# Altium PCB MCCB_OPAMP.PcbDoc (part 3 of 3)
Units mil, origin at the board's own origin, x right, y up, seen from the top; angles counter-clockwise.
Board outline 3937.01 x 3937.01 mil, 2 copper layers (Top Layer, Bottom Layer), stack 62 mil thick; 238 components, 115 nets, 518 pads, 159 vias.
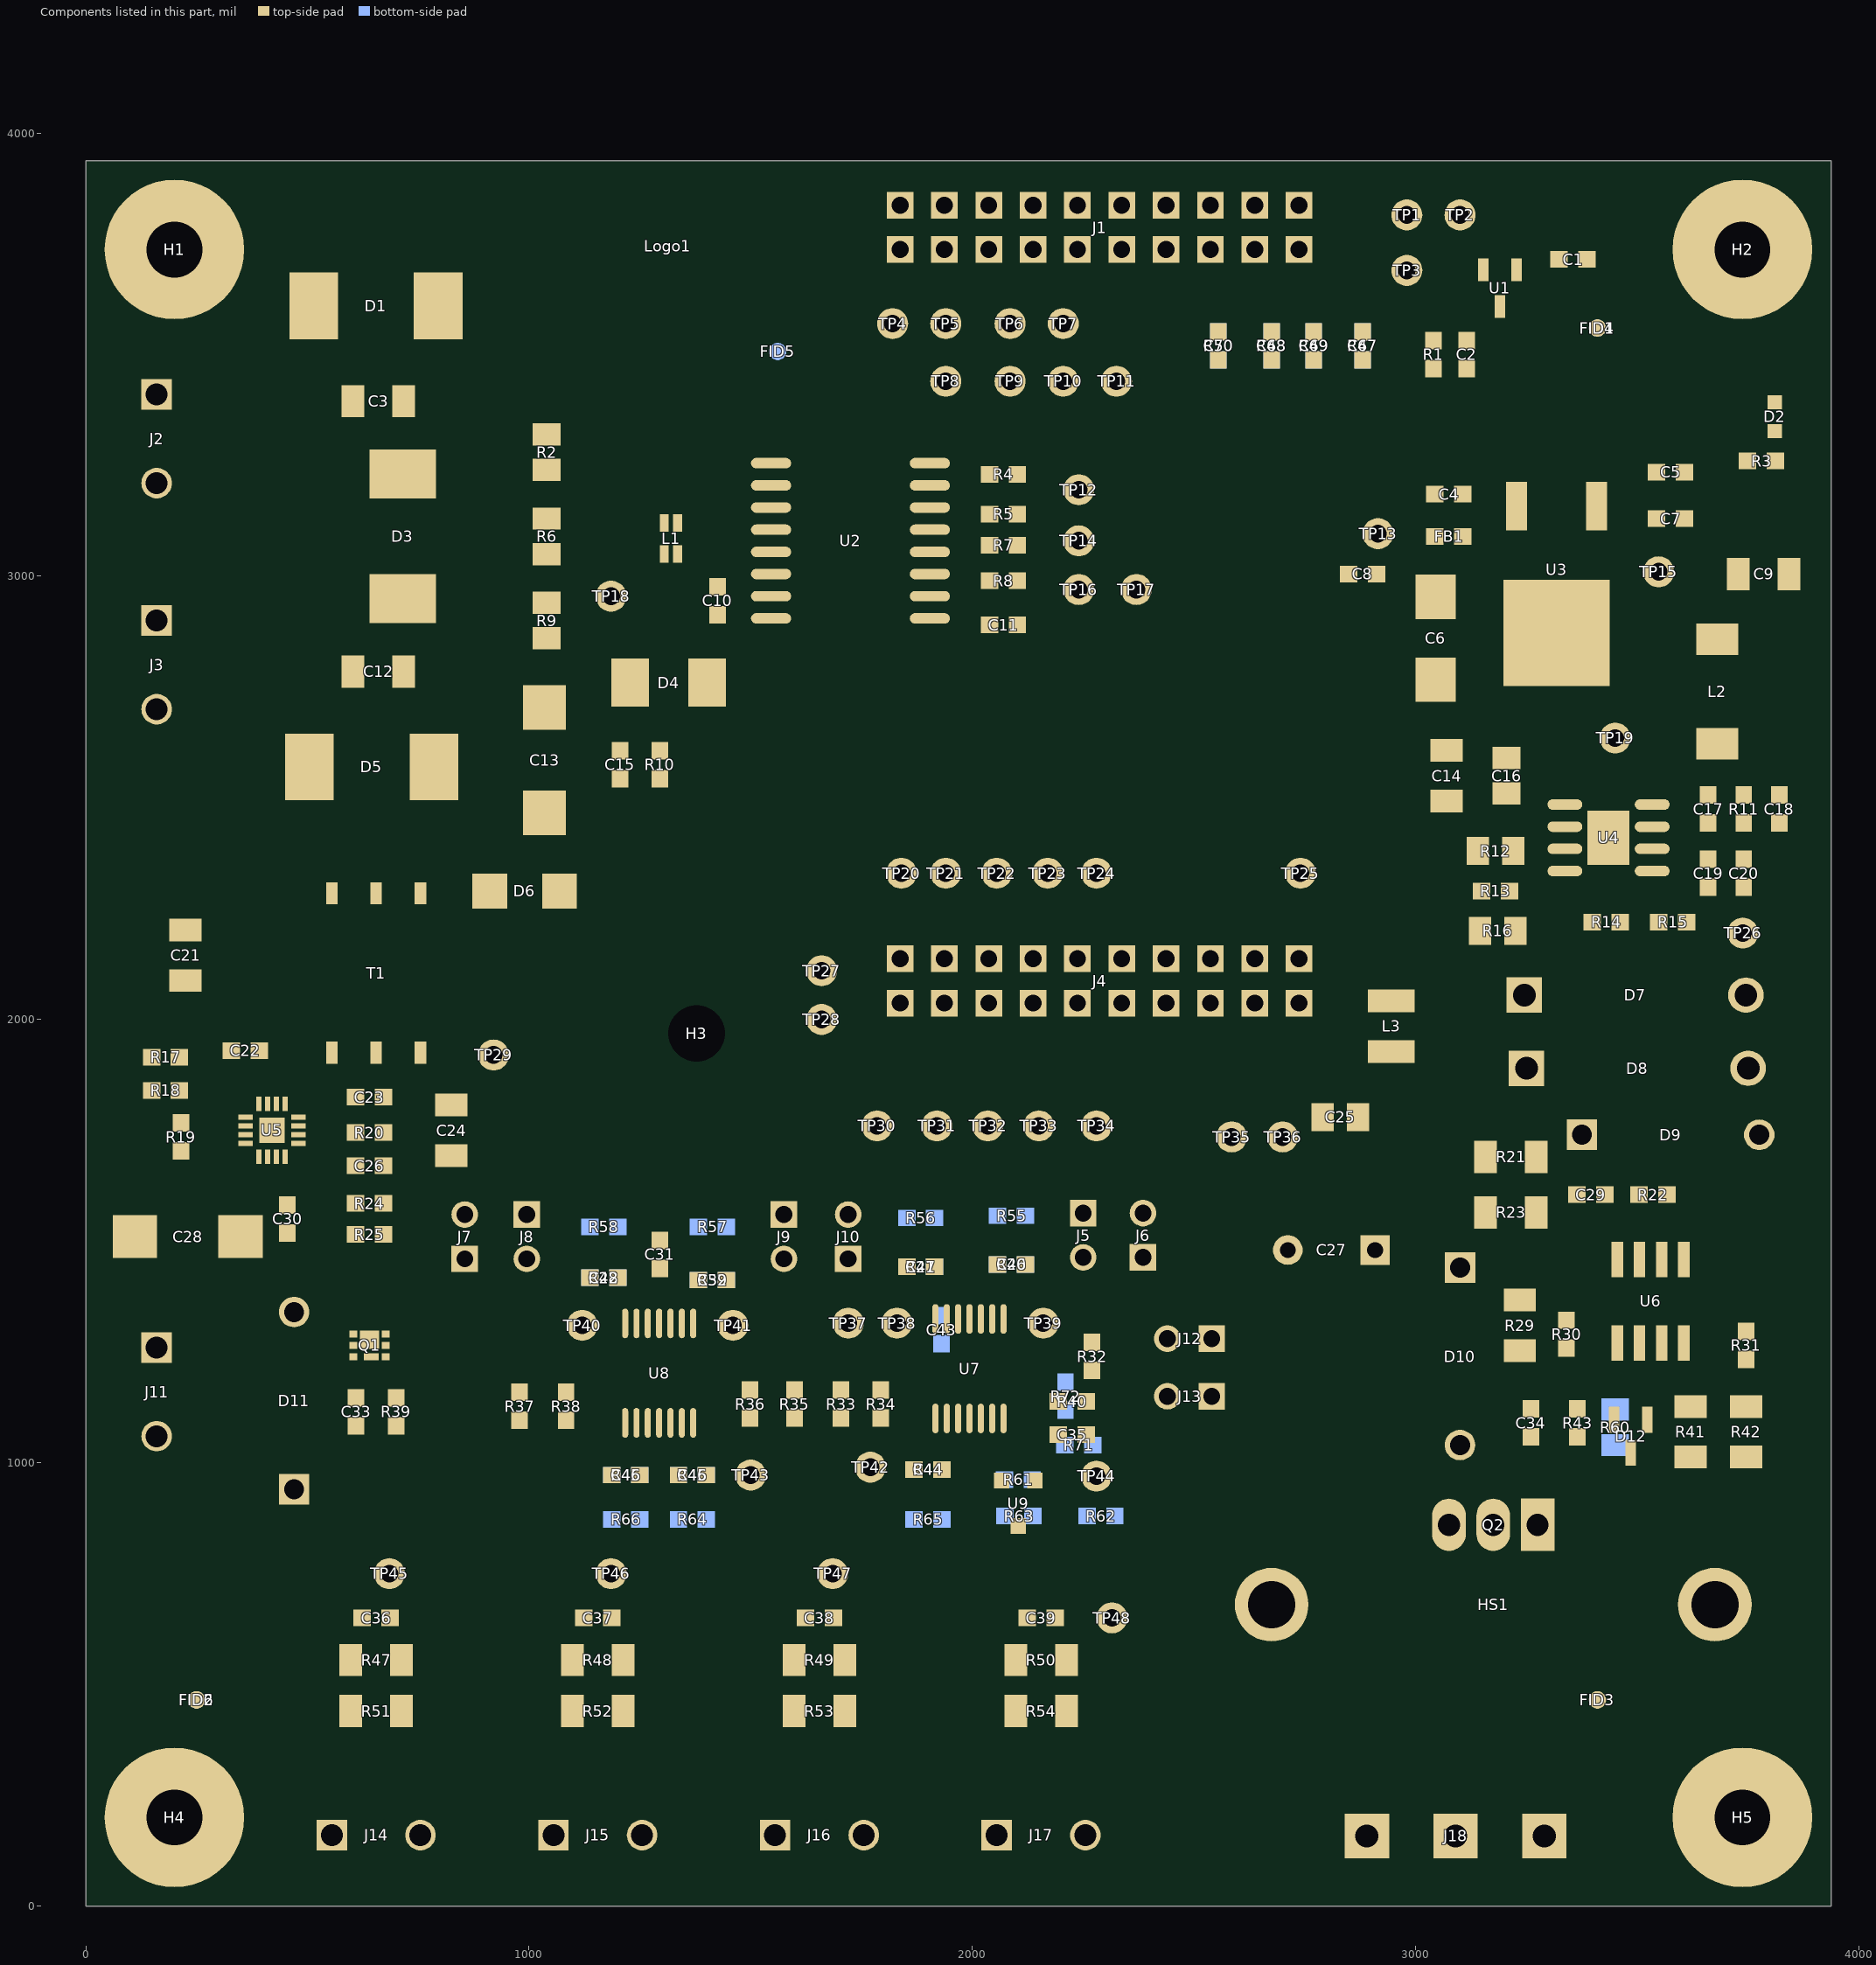
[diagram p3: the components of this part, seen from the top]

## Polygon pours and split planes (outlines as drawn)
GND on Top Layer "Top Layer-No Net" (hatched 90Degree grid 5 track 8, remove dead copper, pour order 57): 1745,2195 1530,2195 1510,2215 1510,2295 1965,2750 2110,2750 2140,2780 2140,2915 2160,2935 2200,2935 2235,2900 2400,2900 2435,2935 2435,3260 2383,3312 2383,3370 2398,3385 2465,3385 2510,3340 2930,3340 3020,3430 3048,3429.82 3055,3421 3055,3185 3030,3160 2900,3160 2880,3180 2765,3180 2750,3165 2750,3145 2780,3115 2780,2575 2810,2545 2810,2415 2780,2385 1935,2385
NetC4_1 on Top Layer "Top Layer-No Net" (hatched 90Degree grid 5 track 8, remove dead copper, pour order 53): 3095,3240 3095,3065 3115,3045 3125,3035 3170,3035 3240,3035 3255,3050 3265,3060 3265,3195 3265,3255 3245,3275 3155,3275 3120,3275 3100,3255 3095,3250 3095,3240
UC3.3V on Top Layer "Top Layer-No Net" (hatched 90Degree grid 5 track 8, remove dead copper, pour order 50): 3065,3120 3065,3040 3100,3005 3100,2910 3075,2885 2805,2885 2795,2895 2795,2950 2805,2960 2885,2960 2895,2970 2895,3050 2855,3090 2855,3125 2870,3140 3045,3140
GND on Top Layer "Top Layer-No Net 1" (hatched 90Degree grid 5 track 8, remove dead copper, pour order 40): 3030,3370 3175,3370 3190,3385 3190,3425 3185,3430 3030,3430 3020,3420 3020,3380
GND on Top Layer "Bottom Layer-No Net" (hatched 90Degree grid 5 track 8, remove dead copper, pour order 74): 3800,3210 3800,3070 3815,3055 3815,2745 3830,2730 3885,2730 3900,2745 3900,3510 3885,3525 3550,3525 3505,3480 3505,3395 3515,3385 3590,3385 3620,3415 3765,3415 3805,3375 3840,3375 3850,3365 3850,3230 3840,3220 3815,3220
12V on Top Layer "Top Layer-No Net" (hatched 90Degree grid 5 track 8, remove dead copper, pour order 41): 3740,2820 3530,2820 3510,2840 3495,2855 3495,3000 3495,3050 3485,3060 3470,3075 3390,3075 3365,3075 3345,3095 3345,3175 3345,3300 3365,3320 3375,3330 3490,3330 3540,3330 3555,3315 3560,3310 3560,3230 3560,3100 3575,3085 3600,3060 3745,3060 3750,3055 3750,2905 3750,2830 3740,2820
GND on Top Layer "Top Layer-No Net 1" (hatched 90Degree grid 5 track 8, remove dead copper, pour order 47): 2425,3345 2400,3320 2050,3320 2010,3360 2010,3375 2020,3385 2420,3385 2425,3380 2460,3380 2465,3375 2465,3350 2460,3345
GND on Top Layer "Top Layer-No Net 1" (hatched 90Degree grid 5 track 8, remove dead copper, pour order 42): 2910,3500 2920,3510 2920,3575 2935,3590 2985,3590 2995,3580 2995,3485 2970,3460 2415,3460 2410,3465 2410,3495 2415,3500
16V_C on Top Layer "Bottom Layer-No Net" (hatched 90Degree grid 5 track 8, remove dead copper, pour order 70): 3180,1340 3285,1340 3310,1365 3310,1420 3315,1425 3460,1425 3460,1495 3385,1570 3385,1655 3415,1685 3415,1890 3375,1930 3215,1930 3205,1920 3205,1800 3245,1760 3245,1505 3165,1425 3165,1355
NetC14_2 on Top Layer "Bottom Layer-No Net" (hatched 90Degree grid 5 track 8, remove dead copper, pour order 72): 3045,2025 3035,2015 2875,2015 2860,2035 2860,2500 2880,2520 3255,2520 3265,2510 3265,2445 3255,2435 3170,2435 3160,2425 3160,2360 3155,2355 3080,2355 3060,2335 3060,2260 3075,2245 3160,2245 3165,2240 3165,2175 3150,2160 3080,2160 3045,2125
GND on Top Layer "Bottom Layer-No Net" (hatched 90Degree grid 5 track 8, remove dead copper, pour order 55): 3140,55 3025,55 3005,75 3000,80 3000,250 3000,920 3020,940 3065,940 3085,940 3095,930 3110,915 3110,805 3090,785 3085,780 3085,735 3085,275 3125,235 3140,220 3145,215 3145,130 3145,60 3140,55
NetD10_2 on Top Layer "Bottom Layer-No Net" (hatched 90Degree grid 5 track 8, remove dead copper, pour order 48): 3135,1130 3150,1115 3150,1020 3210,960 3210,715 3275,650 3275,425 3380,320 3380,90 3350,60 3210,60 3190,80 3190,295 3140,345 3140,930 3060,1010 3060,1120 3070,1130
NetC34_2 on Top Layer "Bottom Layer-No Net" (hatched 90Degree grid 5 track 8, remove dead copper, pour order 43): 3410,735 3435,760 3435,955 3405,985 3405,1060 3395,1070 3255,1070 3245,1060 3245,755 3265,735
PGND on Top Layer "Bottom Layer-No Net" (hatched 90Degree grid 5 track 8, remove dead copper, pour order 66): 925,2590 885,2630 885,2775 910,2800 1080,2800 1150,2870 1250,2870 1260,2860 1260,2600 1250,2590
GND on Top Layer "Bottom Layer-No Net" (hatched 90Degree grid 5 track 8, remove dead copper, pour order 65): 745,1565 670,1565 660,1575 660,1630 660,1830 673,1843 675,1845 718,1845 730,1845 735,1840 735,1816 735,1596 745,1586 745,1580 745,1565
NetC24_1 on Top Layer "Bottom Layer-No Net" (hatched 90Degree grid 5 track 8, remove dead copper, pour order 64): 780,1800 750,1830 750,1950 845,1950 880,1985 995,1985 1005,1975 1005,1820 990,1800
PGND on Top Layer "Bottom Layer-No Net" (hatched 90Degree grid 5 track 8, remove dead copper, pour order 63): 305,2190 145,2190 125,2210 125,2345 130,2350 135,2355 250,2355 310,2355 320,2345 320,2315 320,2200 310,2190 305,2190
NetC22_1 on Top Layer "Bottom Layer-No Net" (hatched 90Degree grid 5 track 8, remove dead copper, pour order 61): 390,1800 430,1800 435,1805 435,1855 445,1865 550,1865 560,1875 560,1935 555,1940 500,1940 465,1975 395,1975 380,1960 380,1810
NetD6_2 on Top Layer "Top Layer-No Net" (hatched 90Degree grid 5 track 8, remove dead copper, pour order 59): 750,2265 735,2280 735,2390 750,2405 930,2405 960,2375 960,2275 950,2265
EGND on Top Layer "Top Layer-No Net" (hatched 90Degree grid 5 track 8, remove dead copper, pour order 45): 410,2425 380,2455 380,2775 465,2860 610,2860 625,2845 625,2730 570,2675 570,2435 560,2425
EGND on Top Layer "Top Layer-No Net" (hatched 90Degree grid 5 track 8, remove dead copper, pour order 51): 415,3515 385,3485 385,3325 405,3305 585,3305 625,3345 625,3790 605,3810 440,3810 415,3785
NetC34_1 on Top Layer "Bottom Layer-No Net" (hatched 90Degree grid 5 track 8, remove dead copper, pour order 69): 3205,1100 3165,1140 3165,1255 3180,1270 3380,1270 3405,1295 3450,1295 3460,1285 3460,1200 3415,1155 3415,1110 3405,1100
39V on Top Layer "Bottom Layer-No Net" (hatched 90Degree grid 5 track 8, remove dead copper, pour order 71): 2870,1410 3120,1410 3120,1465 3190,1535 3190,1720 3155,1755 3155,1935 3190,1970 3310,1970 3320,1980 3320,2100 3305,2115 3110,2115 3095,2100 3095,1985 3075,1965 2870,1965 2850,1945 2850,1430
NetC17_2 on Top Layer "Bottom Layer-No Net" (hatched 90Degree grid 5 track 8, remove dead copper, pour order 73): 3765,2485 3775,2495 3775,2660 3760,2675 3430,2675 3420,2665 3420,2610 3510,2520 3510,2485
GND on Top Layer "Bottom Layer-No Net" (hatched 90Degree grid 5 track 8, remove dead copper, pour order 75): 3465,1015 3815,1015 3845,985 3845,890 3795,840 3790,840 3510,840 3500,850 3460,890 3460,945 3460,1010 3465,1015
C5V on Top Layer "Bottom Layer-No Net" (hatched 90Degree grid 5 track 8, remove dead copper, pour order 76): 1140,2250 1155,2270 1155,2345 1230,2420 1325,2420 1335,2430 1335,2540 1325,2550 1180,2550 1140,2510 1035,2510 1020,2495 1020,2485 1015,2480 1015,2265 1030,2250
12V on Top Layer "Bottom Layer-No Net" (hatched 90Degree grid 5 track 8, remove dead copper, pour order 60): 495,1120 525,1090 525,890 505,870 115,870 80,905 80,1095 105,1120
NetD11_2 on Top Layer "Bottom Layer-No Net" (hatched 90Degree grid 5 track 8, remove dead copper, pour order 56): 695,1265 515,1265 455,1205 115,1205 95,1225 95,1315 110,1330 350,1330 400,1380 695,1380 705,1370 705,1275
GND on Top Layer "Bottom Layer-No Net" (hatched 90Degree grid 5 track 8, remove dead copper, pour order 49): 460,1415 445,1430 445,1515 460,1530 485,1530 500,1545 500,1625 465,1660 440,1660 430,1670 430,1720 510,1720 545,1685 545,1600 570,1575 570,1512.5 578.33,1475 705,1475 720,1460 720,1435 700,1415
GND on Top Layer "Bottom Layer-No Net" (hatched 90Degree grid 5 track 8, remove dead copper, pour order 58): 135,1395 85,1395 70,1410 70,1840 90,1860 160,1860 165,1855 165,1785 140,1760 140,1560 145,1555 145,1405
GND on Top Layer "Bottom Layer-No Net" (hatched 90Degree grid 5 track 8, remove dead copper, pour order 62): 100,2100 345,2100 360,2085 360,2055 360,2050 345,2035 335,2025 220,2025 105,2025 90,2040 90,2080 90,2090 100,2100
UC3.3V on Top Layer "Bottom Layer-No Net" (hatched 90Degree grid 5 track 8, remove dead copper, pour order 54): 465,1575 415,1575 405,1585 385,1585 375,1575 375,1430 365,1420 250,1420 240,1430 240,1605 200,1645 200,1700 215,1715 340,1715 370,1720 370,1690 405,1690 405,1640 430,1615 465,1615
GND on Top Layer "Top Layer-No Net 1" (hatched 90Degree grid 5 track 8, remove dead copper, pour order 44): 1950,1250 1990,1210 2100,1210 2110,1200 2110,1170 2100,1160 2000,1160 1970,1190 1850,1190 1830,1210 1830,1240 1840,1250
GND on Top Layer "Bottom Layer-No Net" (hatched 90Degree grid 5 track 8, remove dead copper, pour order 67): 3475,2310 3410,2245 3410,2150 3430,2130 3500,2130 3650,1980 3785,1980 3825,1940 3825,1285 3805,1265 3630,1265 3600,1295 3600,1755 3355,2000 3355,2280 3395,2320 3395,2460 3385,2470 3310,2470 3300,2480 3300,2548 3283,2565 2880,2565 2840,2605 2840,2785 2860,2805 3135,2805 3170,2840 3170,2965 3200,2995 3440,2995 3460,2975 3460,2850 3460,2825 3460,2745 3380,2665 3380,2610 3475,2515
PGND on Bottom Layer "Bottom Layer-No Net" (hatched 90Degree grid 5 track 8, remove dead copper, pour order 68): 376,2246 450,2320 935,2320 1305,2690 1305,2920 1335,2950 1410,2950 1500,3040 1500,3340 1330,3510 760,3510 650,3400 645,3115 645,3025 630,3010 150,3010 125,2985 125,2840 140,2825 190,2825 310,2945 650,2945 650,2490 570,2410 150,2410 100,2360 100,2260 114,2246
EGND on Bottom Layer "Bottom Layer-No Net" (hatched 90Degree grid 5 track 8, remove dead copper, pour order 39): 475,2895 560,2895 580,2875 580,2581 505,2506 60,2506 35,2531 35,3485 85,3535 500,3535 550,3485 550,3295 520,3265 333,3265 305,3293 305,3445 264,3486 85,3486 70,3471 70,2765 85,2750 415,2750 445,2780 445,2865
GND on Bottom Layer "Bottom Layer-No Net" (hatched 90Degree grid 5 track 8, remove dead copper, pour order 52): 3850,3900 3900,3850 3905,2710 3895,2700 3730,2700 3715,2685 3715,2345 3625,2255 3290,2255 3275,2240 3275,2190 3520,1945 3520,1770 3600,1690 3600,815 3465,680 2920,680 2650,410 590,410 460,540 460,785 560,885 560,1150 520,1190 110,1190 50,1250 50,2080 80,2110 350,2110 470,1990 470,1860 500,1830 969,1830 1020,1881 1020,1970 1040,1990 1210,1990 1990,2770 1990,3240 1950,3280 1950,3540 1780,3710 1780,3880 1800,3900
12V on Bottom Layer "Bottom Layer-No Net" (hatched 90Degree grid 5 track 8, remove dead copper, pour order 46): 3725,3055 3750,3030 3750,2705 3865,2590 3865,440 3840,415 3520,415 3375,270 440,270 325,385 325,755 94,986 94,1116 118,1140 490,1140 525,1105 525,900 415,790 415,436 506,345 2679,345 2979,645 3600,645 3660,705 3660,1060 3630,1090 3633,1983 3550,2066 3550,2135 3755,2340 3755,2500 3505,2750 3505,3030 3530,3055

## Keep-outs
Keep-Out Layer:
  lines w10: 3942.01,2925 3942.01,-5 -20,-5 -20,3948 3942.01,3948 3942.01,3135 ; 4950,3455 cw(c4950,3450) 4955,3450 ; 4950,3455 cw(c4950,3450) 4955,3450 ; 4950,3455 cw(c4950,3450) 4955,3450 ; 4950,3455 cw(c4950,3450) 4955,3450 ; 4950,3455 cw(c4950,3450) 4955,3450 ; 4950,3455 cw(c4950,3450) 4955,3450
  text ".Layer_Name" at 577,-858.49 h60

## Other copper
Top Layer:
  pour cut-out: 3190,3370 3033,3370 3020,3357 3020,3295 3030,3285 3150,3285 3190,3325
  pour cut-out: 2705,3195 2900,3195 2900,3155 2735,3155 2705,3185
  pour cut-out: 776,1820 770,1826 756,1826 745,1815 745,1785 754,1776 773,1776 776,1779
  pour cut-out: 735,1875 745,1875 780,1840 780,1810 777.09,1807.09 752.91,1807.09 745,1815 745,1845 735,1855
  pour cut-out: 1862,2290 1857,2295 1857,2362 1866,2371 1916,2371 1926,2361 1926,2294 1922,2290
  pour cut-out: 605,1475 570,1475 565,1480 565,1590 575,1600 600,1600 615,1585 615,1500 605,1490
  pour cut-out: 780,1835 750,1865 740,1865 740,1790 750,1780 775,1780 780,1785
  text ".Layer_Name" at 577,-858.49 h60
Bottom Layer:
  pour cut-out: 2905,2900 2830,2900 2810,2920 2810,2980 2880.2,2980 2915,2945.2 2915,2910
  pour cut-out: 2500,3440 2685,3440 2685,3540 2690,3545 2683.5,3551.5 2526.5,3551.5 2500,3525
  pour cut-out: 2495,3455 2750,3455 2755,3460 2755,3585 2750,3590 2750,3660 2730,3680 2500,3680 2490,3670 2490,3460
  pour cut-out: 3035,3570 3035,3650 2955,3650 2955,3600 2950,3595 2950,3573 2953,3570
  pour cut-out: 2110,2930 2110,2695 2095,2695 2005,2785 2005,3240 2060,3295 2235,3295 2285.38,3244.62 2285.38,3101 2315,3071.38 2315,3055 2200,2940 2120,2940
  pour cut-out: 1795,910 1795,855 1780,840 1630,840 1605,865 1605,910
  pour cut-out: 2369,960 2309,900 2217,900 2202,915 2202,967 2250,1015 2365,1015 2405,975 2405,960
  pour cut-out: 2281,1095 2260,1116 2260,1161 2300,1201 2597,1201 2615,1183 2615,1102 2608,1095
  pour cut-out: 2415,1495 2415,1782.01 2358.5,1838.5 1898.5,1838.5 1865,1805 1865,1470 1885,1450 2150,1450 2160,1440 2335,1440 2390,1495
  pour cut-out: 1998,1290 2025,1317 2025,1375 2045.46,1395.46 2163.46,1395.46 2178,1410 2178,1605 2108,1675 1877,1675 1815,1613 1815,1325 1850,1290
  pour cut-out: 1615,1545 1615,1521 1651,1485 1760,1485 1760,1530.5 1755.5,1535 1690,1535 1680,1545
  pour cut-out: 2010,1310 2010,1375 1974.5,1410.5 1880.5,1410.5 1845,1375 1845,1320 1855,1310
  pour cut-out: 1805,1010 1860,1065 1880,1065 1880,965 1870,955 1810,955 1810,965 1805,970
  pour cut-out: 1770,900 1775,895 1973,895 1973,937 1955,955 1770,955
  pour cut-out: 1685,790 1685,835 1670,850 1625,850 1615,840 1615,825 1655,785 1680,785
  pour cut-out: 3500,991 3563,1054 3563,1185 3542,1206 3405,1206 3388,1189 3388,998 3395,991
  pour cut-out: 3617,1494 3533,1494 3510,1517 3510,1530 3559,1579 3559,1708 3578,1727 3607,1727 3621,1713 3621,1498
  pour cut-out: 3151,776 3121.6,805.4 3121.6,927.6 3155,961 3225,961 3240,946 3328,946 3339,935 3339,787 3328,776
  pour cut-out: 1645,2076 1645,2015 1660,2000 1745,2000 1762,2017 1762,2035 1705,2092 1644,2092 1644,2077
  pour cut-out: 1886,1810 1876,1820 1735,1820 1731,1816 1731,1709 1745,1695 1837,1695 1841,1691 1841,1667 1855,1653 1880,1653 1886,1659
  pour cut-out: 1486,1340 1486,1602 1439,1649 1410,1649 1410,1355 1433,1332 1484,1332 1484,1334 1487,1337
  pour cut-out: 1360,1535 1344.36,1535 1343.36,1536 1343.36,1596.36 1352,1605 1374.5,1605 1377.5,1602 1377,1601.5 1377,1544 1368,1535 1361,1535 1360,1534
  pour cut-out: 1816,1351 1809,1351 1805,1355 1805,1407.64 1813.36,1416 1826.07,1416 1831.07,1411 1832,1411 1832,1359 1828,1355 1820,1355
  pour cut-out: 1856,1340 1856,1367 1881,1392 1881,1429 1858,1429 1840,1411 1840,1353 1853,1340
  pour cut-out: 1817,1384 1817,1457 1820,1460 1824,1460 1831,1453 1831,1395 1822,1386 1822,1383 1818,1383
  pour cut-out: 1645,1216 1640,1221 1660,1241 1678,1241 1684,1235 1684,1218 1682,1216
  pour cut-out: 1730,1278 1730,1238 1723,1231 1688,1231 1678,1241 1682,1245 1682,1258 1683,1258 1704,1279 1729,1279
  pour cut-out: 740,3050 740,3110 730,3120 610,3120 610,3060 680,3060 690,3050
  pour cut-out: 2785,2191 2800,2176 2800,2016 2764,1980 1798,1980 1770,2008 1770,2171 1790,2191
  pour cut-out: 2785,3891 2800,3876 2800,3716 2764,3680 1798,3680 1770,3708 1770,3871 1790,3891
  pour cut-out: 1890,3500 1930,3460 2350,3460 2370,3480 2370,3730 2320,3780 1770,3780 1740,3750 1740,3530 1770,3500
  pour cut-out: 2994,3884 2978,3900 2978,3922 2970,3930 1790,3930 1750,3890 1750,3790 2520,3790 2550,3760 2550,3670 2570,3650 2840,3650 2880,3610 2880,3570 2994,3570
  pour cut-out: 810,1550 810,1470 900,1470 960,1530 960,1590 950,1600 860,1600
  pour cut-out: 1069.5,1609 1080.5,1598 1080.5,1553 1050.5,1523 870.5,1523 850.5,1543 850.5,1593 866.5,1609
  pour cut-out: 1278,1009.97 1313,1009.97 1313,839.57 1308,834.57 1286.43,834.57 1277,844 1277,1008.97
  pour cut-out: 1347,1600 1347,1547 1353,1541 1410,1541 1424,1555 1424,1584 1406,1602 1349,1602
  pour cut-out: 1232,1602 1238.72,1595.28 1238.72,1385.29 1229.44,1376 1159,1376 1148,1387 1148,1588 1162,1602
  pour cut-out: 815,1365 800,1380 800,1586 823,1609 896,1609 908,1597 908,1368 905,1365
  pour cut-out: 2174.7,842.3 2160,857 2051,857 2044,864 2044,908.52 2041.52,911 1784,911 1778,917 1778,956 1785,963 1956,963 1962,969 1962,999 1969,1006 2168,1006 2230,1010 2252,1002 2296,958 2296,845.3 2293,842.3
  pour cut-out: 3004,3911 2987,3928 2939,3928 2921,3910 2921,3793 2939,3775 2995,3775 3002,3782 3004,3782
  pour cut-out: 3235,801.94 3151.46,801.94 3130,823.41 3130,936 3154,960 3220,960 3235,945
  pour cut-out: 2320,1260 2490,1430 2490,1580 2450,1620 2330,1620 2210,1500 2210,1270 2168,1228 2168,1002 2190,980 2300,980 2320,1000
  pour cut-out: 2560,1520 2480,1520 2480,1440 2490,1430 2548,1430 2560,1442
  pour cut-out: 1980,1010.7 1968,1022.7 1887.7,1022.7 1880,1015 1880,960 1894,946 1964,946 1978,960 1990,970 1990,1000
  pour cut-out: 1460,2100 1460,2300 1440,2320 1350,2320 1310,2280 1310,2160 1370,2100
  pour cut-out: 2450,1580 2540,1580 2550,1570 2550,1540 2530,1520 2460,1520 2440,1540 2440,1570
  pour cut-out: 1910,2310 1910,2360 1860,2360 1860,2310
  pour cut-out: 2040,2740 2060,2760 1970,2850 1920,2850 1900,2830 1900,2760 1920,2740
  pour cut-out: 2010,3250 1930,3250 1930,3200 1940,3190 2020,3190 2030,3200 2030,3230
  pour cut-out: 3520,1560 3520,1771 3569,1771 3578,1762 3578,1578 3560,1560
  pour cut-out: 2665,3445 2801.7,3445 2807.7,3451 2807.7,3588.64 2803,3593.34 2803,3619.13 2782.13,3640 2740,3640 2740,3585 2665,3510
  pour cut-out: 2843.3,3570 2842.3,3571 2842.3,3661.3 2846,3665 2905,3665 2915,3655 2915,3582 2903,3570
  text ".Layer_Name" at 577,-858.49 h60

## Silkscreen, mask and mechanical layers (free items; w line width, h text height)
Top Overlay:
  circle w8: c582.12,1421 r40
  circle w8: c113.12,882 r40
  circle w15: c3521,3178 r6
  circle w15: c3549,1146 r6
  circle w15: c1383,3047 r6
  circle w15: c2213,959 r6
  lines w6: 2800,3450 2800,3415 2810,3405 ; 2865,3450 2865,3430 2880,3415
  lines w8: 483,1658 329.15,1658 329.15,1842.15 512.05,1842.15 512.05,1689.95 ; 711,1813 711,1866 569,1866 569,1465 713,1465 713,1601 ; 713,1657 713,1753 ; 1839.63,3459.99 1906.32,3526.68 ; 1941,2374 1941,2447 ; 2037,1812 2037,1877 ; 2131,2637 2131,2822 ; 2173,2384 2173,2451 ; 2790,88 3390,88 ; 2845,649 2845,429 2522,429 2522,834 2845,834 2845,711 ; 2847,649 3505,649 3505,429 3828,429 3828,834 3505,834 3505,711 2847,711 ; 2989,1 2989,88 ; 3190,1 3190,88 ; 3767.27,2415.02 3789.28,2393 ; 3823,2220 3790.01,2220 3756.01,2254 3695,2254 ; 2131,2822 2142,2811 2120,2811 2131,2822 ; 3695,2254 3703,2246 3703,2262 3695,2254 ; 154,592 327,592 327,888 327,926 154,926 154,611 154,592 ; 1275,3015 1275,3155 1365,3155 1365,3015 1275,3015 ; 2013.54,822.27 2013.54,992.27 2193.54,992.27 2193.54,822.27 2013.54,822.27 ; 2790,1 2790,355 3390,355 3390,1 2790,1 ; 3415,1215 3645,1215 3645,1514 3415,1514 3415,1215
  text "19" at 1721,3873 h40
  text "1" at 2805,3837.01 h40
  text "2" at 2725,3635 h40
  text "20" at 1793,3631 h40
  text "ISE-MCCB-DAFE-100" at 935,3530 h40
  text "SAT0079  Rev E2" at 1005,3435 h40
  text "1" at 2725,2205 h40
  text "19" at 1787.06,2201 h40
  text "2" at 2725,1937.01 h40
  text "20" at 1790,1925 h40
  text "A" at 571,1403 h40
  text "A" at 102,864 h40
  text "1" at 2880,372 h40
  text "3" at 3280,369 h40
  text ".Layer_Name" at 577,-858.49 h40
Bottom Overlay:
  lines w6: 2740,3390 2740,3445 2750,3455
  text ".Layer_Name" at 577,-858.49 h40
Top Paste:
  text ".Layer_Name" at 577,-858.49 h60
Bottom Paste:
  text ".Layer_Name" at 577,-858.49 h60
Top Solder:
  text ".Layer_Name" at 577,-858.49 h60
  text ".Layer_Name" at 577,-858.49 h60
Bottom Solder:
  text ".Layer_Name" at 577,-858.49 h60
Drill Guide:
  text ".Layer_Name" at 577,-858.49 h60
M1 Board Outline:
  the board outline again, w10
  text ".Layer_Name" at 577,-858.49 h60
M2 Board Dimensions:
  rectangle: 124.5,-410.5 499.5,-285.5
  rectangle: -0.5,-285.5 124.5,-160.5
  lines w7: -0.5,-285.5 999.5,-285.5 ; 124.5,-410.5 124.5,-160.5 ; 249.5,-410.5 249.5,-160.5 ; 499.5,-410.5 499.5,-160.5 ; 749.5,-410.5 749.5,-160.5 ; -0.5,-410.5 -0.5,-160.5 999.5,-160.5 999.5,-410.5 -0.5,-410.5
  lines w10: -0.5,-475.5 -0.5,-455.5 ; 59.5,-485.5 -0.5,-465.5 ; 59.5,-445.5 -0.5,-465.5 ; 223.58,-465.5 -0.5,-465.5 ; 775.42,-465.5 999.5,-465.5 ; 939.5,-485.5 999.5,-465.5 ; 939.5,-445.5 999.5,-465.5 ; 999.5,-475.5 999.5,-455.5
  text "1000 (mil)" at 233.58,-501.49 h60
  text ".Layer_Name" at 577,-858.49 h60
M3 3D STEP Top:
  text ".Layer_Name" at 577,-858.49 h60
M4 3D STEP Bottom:
  text ".Layer_Name" at 577,-858.49 h60
M5 Assembly Top:
  circle w20: c3549,1146 r6
  circle w20: c3226,3746 r6
  circle w30: c555,1974 r6
  lines w6: 3794.25,3348.58 3794.25,3371.42 ; 3825.75,3348.58 3825.75,3371.42
  lines w8: 3843.95,3371.64 3893.95,3371.64 ; 3868.95,3321.64 3868.95,3346.64 ; 3868.95,3396.64 3868.95,3371.64 ; 3868.95,3371.64 3893.95,3346.64 3843.95,3346.64 3868.95,3371.64 ; 505,1885.63 505,2326.57 805,2326.57 805,1885.63 505,1885.63 ; 3130.94,3587 3249.06,3587 3249.06,3725.06 3130.94,3725.06 3130.94,3648 3130.94,3587
  lines w10: -292,-930.17 6308,-930.17 ; -292,-726.83 6310,-726.83 ; -292,-523.5 -292,-1133.5 3713,-1133.5 6310,-1133.5 6310,-523.5 -291.5,-523.5 -291.5,-1133.5 1284,-1133.5 ; 2173,-1133.5 2173,-523.5 ; 3890,-726.83 3890,-523.5 ; 4902,-1140 4902,-937.17 ; 4915,-726.83 4915,-523.5
  text "D2" at 3708,3341 h40
  text "T1" at 615,2080 h40
  text "9" at 440,1851 h40
  text "13" at 260,1780 h40
  text "5" at 523,1691 h40
  text "1" at 2761,147 h40
  text "COMPONENTS MARKED 'DNP' SHOULD NOT BE POPULATED." at 1153.5,-318.5 h40
  text "ASSEMBLY VARIANT:" at 1153,-434 h40
  text ".VariantName" at 2189,-434 h40
  text "PCB VIEWED FROM TOP SIDE" at -228.5,-655.67 h40
  text "BOARD #:" at 2248,-655.67 h40
  text "ISE-MCCB-DAFE-100" at 2793.5,-655.67 h40
  text "REV:" at 4135,-655.67 h40
  text ".PCB_Rev" at 4455,-655.67 h40
  text ".VersionControl_RevNumber" at 4982,-655.67 h40
  text "IGNORE ->" at -228.5,-858.49 h40
  text "PLOT NAME =" at -228.5,-1064.34 h40
  text ".plot_File_Name" at 577,-1064.34 h40
  text "GENERATED    :" at 2250,-1064.34 h40
  text ".Print_Date" at 3119.5,-1064.34 h40
  text ".Print_Time" at 3848.5,-1064.34 h40
  text "TEXAS INSTRUMENTS" at 5113,-1064.34 h40
M6 Assembly Bottom:
  lines w10: -292.5,-727.33 6309.5,-727.33 ; -290.5,-930.67 6309.5,-930.67 ; 1115.5,-1140.5 1115.5,-937.67 ; 1737.5,-727.33 1737.5,-524 ; 2577.5,-727.33 2577.5,-524 ; 3844.5,-1134 3844.5,-524 ; 4733.5,-1134 6309,-1134 6309,-524 -292.5,-524 -292.5,-1134 2304.5,-1134 6309.5,-1134 6309.5,-524
  text "COMPONENTS MARKED 'DNP' SHOULD NOT BE POPULATED." at 6102,-318 h36
  text ".VariantName" at 5058,-434 h36
  text "ASSEMBLY VARIANT:" at 6097,-434 h36
  text ".VersionControl_RevNumber" at 1035.5,-656.17 h36
  text "SVN REV:" at 1541.5,-656.17 h36
  text ".PCB_Rev" at 2088,-656.17 h36
  text "REV:" at 2379.5,-656.17 h36
  text ".PRJ_Number" at 3224,-656.17 h36
  text "BOARD #:" at 3769.5,-656.17 h36
  text "PCB VIEWED FROM BOTTOM SIDE" at 6246,-656.17 h36
  text "IGNORE ->" at 2547.85,-858.49 h36
  text "TEXAS INSTRUMENTS" at 904.5,-1064.84 h36
  text ".Print_Time" at 2169,-1064.84 h36
  text ".Print_Date" at 2898,-1064.84 h36
  text "GENERATED    :" at 3767.5,-1064.84 h36
  text ".plot_File_Name" at 5440.5,-1064.84 h36
  text "PLOT NAME =" at 6246,-1064.84 h36
M7 LPKF Text Top:
  lines w10: 1337.01,1937.01 3937.01,1937.01 3937.01,3937.01 1337.01,3937.01 1337.01,1937.01
M9 Title Sheet:
  drawing of 57 lines, arcs and shapes, not listed
  text "1" at 739.84,8036.5 h70
  text "2" at 3235.5,8036.5 h70
  text "3" at 5724.84,8036.5 h70
  text "4" at 8231.51,8036.5 h70
  text "5" at 10730.5,8036.5 h70
  text "6" at 13235.5,8036.5 h70
  text "A" at -416.5,6893.5 h70
  text "A" at 14383.5,6893.5 h70
  text "B" at -416.5,4513.5 h70
  text "B" at 14383.5,4513.5 h70
  text "C" at -416.5,2138.5 h70
  text "C" at 14383.5,2138.5 h70
  text "PROJECT TITLE:" at 11343.5,277.5 h45
  text ".PRJ_Title" at 11393.5,144.17 h70
  text "DESIGNED FOR:" at 11343.5,-23.5 h45
  text ".PRJ_Customer" at 11393.5,-163.5 h70
  text "D" at -416.5,-231.5 h70
  text "D" at 14383.5,-231.5 h70
  text "FILE NAME:" at 11343.5,-323.5 h45
  text "ISE-MCCB-DAFE-100" at 11393.5,-443.5 h70
  text "Texas Instruments (TI) and/or its licensors do not warrant the accuracy or completeness of this specification" at 6374,-605.34 h45
  text "ENGINEER:" at 11343.5,-613.5 h45
  text "LAYOUT BY:" at 12848.5,-613.5 h45
  text "or any information contained therein. TI and/or its licensors do not warrant that this design will meet" at 6329.01,-718 h45
  text "the specifications, will be suitable for your application or fit for any particular purpose, or will operate in" at 6329.01,-830.67 h45
  text ".Layer_Name" at 577,-858.49 h60
  text "ALTIUM DESIGNER VERSION:" at 12848.5,-923.5 h45
  text "an implementation. TI and/or its licensors do not warrant that the design is production worthy. You should" at 6329.01,-943.33 h45
  text "completely validate and test your design implementation to confirm the system functionality for your application." at 6374,-1056 h45
  text ".print_Scale" at 11393.5,-1056.83 h70
  text ".Application_BuildNumber" at 12899,-1056.83 h70
  text "1" at 739.84,-1263.5 h70
  text "2" at 3235.5,-1263.5 h70
  text "3" at 5724.84,-1263.5 h70
  text "4" at 8231.51,-1263.5 h70
  text "5" at 10730.5,-1263.5 h70
  text "6" at 13235.5,-1263.5 h70
M10 Fab Notes:
  drawing of 212 lines, arcs and shapes, not listed
  text "DESIGN INFORMATION" at 12381.02,6806.5 h60
  text "(REFER ALSO ARRAY/PANEL PROFILING INFORMATION)" at 12019.46,6644.79 h60
  text "BOARD SIZE" at 11333.46,6640.5 h60
  text "3937MIL" at 11795.78,6512.68 h60
  text "X" at 12301.46,6512.68 h60
  text "3937MIL" at 12532.78,6512.68 h60
  text "Number of Layers :" at 11736.46,6315.5 h60
  text "2" at 12831.27,6305.5 h60
  text "10" at 12832.7,6176.5 h60
  text "MIN. TRACK WIDTH:" at 11736.46,6176.5 h60
  text "MIL" at 12987.46,6176.5 h60
  text "MIN. CLEARANCE:" at 11736.46,6044.5 h60
  text "MIL" at 12987.46,6044.5 h60
  text "6.85" at 12734,6037 h60
  text "26" at 12802.71,5912.5 h60
  text "MIN. VIA PAD SIZE:" at 11736.46,5912.5 h60
  text "MIL" at 12987.46,5912.5 h60
  text "0.177 (7MIL)" at 12431.46,5770.79 h60
  text "MINIMUM ANNULAR RING" at 11407.23,5766.5 h60
  text "EXTERNAL" at 13139.46,5766.5 h60
  text "PER" at 11607.23,5648.5 h60
  text "IPC-D-275 CLASS 2 LEVEL C" at 11827.23,5648.5 h60
  text "+/-" at 12923,5535.5 h60
  text "MIL, HOLES" at 13315.46,5536.21 h60
  text "+/-" at 13777,5535.5 h60
  text "REGISTRATION TOLERANCES:" at 11407.23,5530.5 h60
  text "METAL" at 12607,5530.5 h60
  text "5" at 13183.2,5530.5 h60
  text "3" at 14016.2,5530.5 h60
  text "MIL" at 14132.46,5530.5 h60
  text "MATERIAL:" at 11332.46,5321.04 h60
  text "FR-4 High Tg" at 12318.9,5180.71 h60
  text "FR-408" at 11753.46,5172.14 h60
  text "X" at 12165.46,5172.14 h60
  text "OTHER" at 13241.46,5172.14 h60
  text "62 MIL (1.6mm) +/-10%" at 12073.56,5009.42 h60
  text "THICKNESS:" at 11407.23,5005.14 h60
  text "X" at 11945.4,5005.14 h60
  text "OTHER" at 13358.46,5005.14 h60
  text "TOLERANCE:" at 11407.23,4847.14 h60
  text "X" at 12246.53,4847.14 h60
  text "ANSI IPC-6012 TYPE 3 CLASS 2" at 12433.48,4847.14 h60
  text "OTHER +/-" at 12433.46,4691.14 h60
  text "BOW & TWIST:" at 11407.23,4534.14 h60
  text "X" at 12246.53,4534.14 h60
  text "ANSI IPC-6012 TYPE 3 CLASS 2" at 12433.48,4534.14 h60
  text "OTHER +/-" at 12433.46,4375.63 h60
  text "COPPER THICKNESS (FINISHED):" at 11332.46,4240.14 h60
  text "1.4MIL (1oz)" at 12212.46,4087.42 h60
  text "2MIL (1.4oz)" at 12979.46,4087.42 h60
  text "2.8MIL (2oz)" at 13706.46,4087.42 h60
  text "OUTER:" at 11689.46,4083.14 h60
  text "X" at 12084,4082.5 h60
  text "N/A" at 13706,3930.79 h60
  text "1.4MIL (1oz)" at 12212.46,3930.42 h60
  text "2.8MIL (2oz)" at 12979.46,3930.42 h60
  text "INNER SIGNAL:" at 11400.38,3926.14 h60
  text "X" at 12085.42,3926.14 h60
  text "DRILLING:" at 11332.46,3787.14 h60
  text "REFERENCE:" at 11407.23,3670.14 h60
  text "X" at 12055.46,3670.14 h60
  text "AS SHOWN" at 12242.46,3670.14 h60
  text "X" at 12956.46,3670.14 h60
  text "NC_DRILL FILES" at 13093.46,3670.14 h60
  text "PTH MIN COPPER THICKNESS:" at 11407.23,3512.14 h60
  text "X" at 12757.46,3512.14 h60
  text "1MIL" at 12894.46,3512.14 h60
  text "OTHER" at 13391.46,3512.14 h60
  text "BOARD FINISH:" at 11332.46,3353.14 h60
  text "SILKSCREEN:" at 11487.68,3235.14 h60
  text "X" at 12436.46,3235.14 h60
  text "TOP" at 12562.46,3235.14 h60
  text "X" at 12946.46,3235.14 h60
  text "BOTTOM" at 13073.46,3235.14 h60
  text "SILKSCREEN COLOR:" at 11487.68,3068.14 h60
  text "X" at 12435.42,3068.14 h60
  text "WHITE" at 12562.46,3068.14 h60
  text "OTHER" at 13073.46,3068.14 h60
  text "SOLDER RESIST COLOR:" at 11487.68,2898.14 h60
  text "X" at 12055.42,2738.94 h60
  text "GREEN" at 12182.46,2738.94 h60
  text "BLUE" at 12773.46,2738.94 h60
  text "OTHER" at 13311.46,2738.94 h60
  text "IMMERSION GOLD (ENIG)" at 12393.46,2550.42 h60
  text "ENEPIG" at 13731,2547.14 h60
  text "SURFACE FINISH:" at 11332.46,2546.14 h60
  text "X" at 12206.51,2546.14 h60
  text "IMM. TIN/SILVER OR EQUIV" at 11662,2389.14 h60
  text "OTHER" at 13093.46,2389.14 h60
  text "ARRAY/PANEL:" at 11332.46,2210.14 h60
  text "CUT AND TRIM PER MECH LAYER 1" at 12393.46,2205.85 h60
  text "N.C. ROUTE" at 12393.46,2054.14 h60
  text "X" at 13072.46,2054.14 h60
  text "V. SCORE" at 13259.46,2054.14 h60
  text "CERTIFICATION:" at 11332.46,1917.14 h60
  text "MATERIALS AND WORKMANSHIP FOR ALL PCBS" at 12057.46,1917.14 h60
  text "TO MEET OR EXCEED THE REQUIREMENTS OF:" at 12057.46,1819.14 h60
  text "X" at 11683.96,1682.63 h60
  text "ANSI IPC-A-600F CLASS ->" at 11822.96,1682.63 h60
  text "X" at 13462.02,1682.63 h60
  text "2" at 13580.96,1682.64 h60
  text "1" at 13265.96,1681.14 h60
  text "3" at 13934.96,1681.14 h60
  text "X" at 11686.02,1523.14 h60
  text "UL 94V-0" at 11822.96,1523.14 h60
  text "X" at 12498.02,1523.14 h60
  text "RoHS" at 12634.96,1523.14 h60
  text "OTHER" at 13279.36,1523.14 h60
  text "PER ORDER" at 13676.42,1523.14 h60
  text "ADDITIONAL REQUIREMENTS:" at 11332.46,1382.14 h60
  text "MICROSECTION:" at 11407.23,1267.14 h60
  text "YES" at 12312.96,1267.14 h60
  text "REQUIRED" at 13174.46,1110.99 h60
  text "BARE BOARD ELEC. TEST:" at 11407.23,1108.14 h60
  text "NONE" at 12712.96,1108.14 h60
  text "X" at 13047.46,1108.14 h60
  text "PER ORDER" at 13766.46,1108.14 h60
  text "MANUFACTURER'S UL:" at 11407.23,951.14 h60
  text "RAIL" at 12572.96,946.85 h60
  text "METAL" at 13064.77,946.85 h60
  text "SILK" at 13576.46,946.85 h60
  text "X" at 13440,946.5 h60
M11 Gerber Information:
  lines w10: -292,-930.17 6308,-930.17 ; -292,-726.83 6310,-726.83 ; -292,-523.5 -292,-1133.5 3713,-1133.5 6310,-1133.5 6310,-523.5 -291.5,-523.5 -291.5,-1133.5 1284,-1133.5 ; 2173,-1133.5 2173,-523.5 ; 4300,-726.83 4300,-523.5 ; 4902,-1140 4902,-937.17 ; 4915,-726.83 4915,-523.5
  text "REV:" at 4350,-650 h60
  text ".PCB_Rev" at 4620,-650 h60
  text "ALL ARTWORK VIEWED FROM TOP SIDE" at -228.5,-655.67 h60
  text "BOARD #:" at 2248,-655.67 h60
  text ".PRJ_Number" at 2793.5,-655.67 h60
  text ".VersionControl_RevNumber" at 4982,-655.67 h60
  text "LAYER NAME =" at -228.5,-858.49 h60
  text "TIDA-00128 OPAMP BASED MCCB ETU" at 2415,-865 h60
  text "PLOT NAME =" at -228.5,-1064.34 h60
  text ".plot_File_Name" at 577,-1064.34 h60
  text "GENERATED    :" at 2250,-1064.34 h60
  text ".Print_Date" at 3119.5,-1064.34 h60
  text ".Print_Time" at 3848.5,-1064.34 h60
  text "TEXAS INSTRUMENTS" at 5113,-1064.34 h60
M12 Stackup:
  lines w6: 11360,7460 13910,7460 ; 11360,7564.4 13910,7564.4 ; 11300,6975 ccw(c11334,6975) 11334,6941 13936,6941 ccw(c13936,6975) 13970,6975 13970,7681 ccw(c13936,7681) 13936,7715 11334,7715 ccw(c11334,7681) 11300,7681 11300,6975
  text "The Stackup Legend below this is static." at 11605.5,7874.5 h60
  text "If you change the stackup, update the Legend." at 11615.5,7784.5 h60
  text "Layer Stack Up Detail for: Ref_Design.PcbDoc" at 11360,7597.1 h57
  text "Layer" at 11360,7525.4 h24
  text "Gerber" at 12255.81,7525.4 h24
  text "Copper" at 12819.33,7525.4 h24
  text "Dielectric" at 13422.04,7525.4 h24
  text "Name" at 11360,7477.4 h24
  text "Document" at 12255.81,7477.4 h24
  text "Thickness" at 12819.33,7477.4 h24
  text "Material" at 13422.04,7477.4 h24
  text "Top Solder Mask" at 11360,7384.44 h34
  text "(.GTS)" at 12255.81,7384.44 h34
  text "Solder Resist" at 13422.04,7384.44 h34
  text "Top Layer" at 11360,7287.69 h34
  text "(.GTL)" at 12255.81,7287.69 h34
  text "1.4mil" at 12819.33,7287.69 h34
  text "FR-4" at 13422.04,7239.31 h34
  text "Bottom Layer" at 11360,7190.94 h34
  text "(.GBL)" at 12255.81,7190.94 h34
  text "1.4mil" at 12819.33,7190.94 h34
  text "Bottom Solder Mask" at 11360,7094.19 h34
  text "(.GBS)" at 12255.81,7094.19 h34
  text "Solder Resist" at 13422.04,7094.19 h34
M13 Component Bodies Top:
  text ".Layer_Name" at 577,-858.49 h60
M14 Component Bodies Bottom:
  text ".Layer_Name" at 577,-858.49 h60
M15 Courtyards Top:
  text ".Layer_Name" at 577,-858.49 h60
M16 Courtyards Bottom:
  text ".Layer_Name" at 577,-858.49 h60
Drill Drawing:
  text ".legend" at 4542.5,715.5 h60
  text "Drill Table" at 4567.5,530.5 h60
  text "FOR PTH +/-3MILS" at 5639.15,354.42 h60
  text "DRILL TOLERANCES:" at 4569.73,348.9 h60
  text "FOR NPTH +/-2MILS" at 5630.86,210.73 h60
  text ".Layer_Name" at 577,-858.49 h60

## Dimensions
2737.01,3837.01 to 3937.01,3937.01 on M7 LPKF Text Top
1337.01,3937.01 to 3937.01,3937.01 on M7 LPKF Text Top
2737.01,3837.01 to 1337.01,3937.01 on M7 LPKF Text Top
0,0 to 3937.01,0 on M2 Board Dimensions
0,0 to 0,3937.01 on M2 Board Dimensions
